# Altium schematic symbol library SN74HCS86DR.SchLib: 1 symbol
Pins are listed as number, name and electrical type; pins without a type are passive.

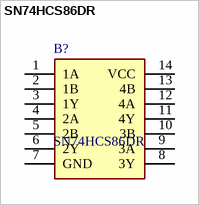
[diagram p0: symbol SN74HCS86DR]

## SN74HCS86DR
designator B?
Logic Gates Quadruple 2-input XOR gates with Schmitt-trigger inputs; Manufacturer_Name: Texas Instruments; Geometry.Height: 1.75mm
footprint SOIC127P600X175-14N
pins: 1 1A, 2 1B, 3 1Y, 4 2A, 5 2B, 6 2Y, 7 GND, 8 3Y, 9 3A, 10 3B, 11 4Y, 12 4A, 13 4B, 14 VCC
